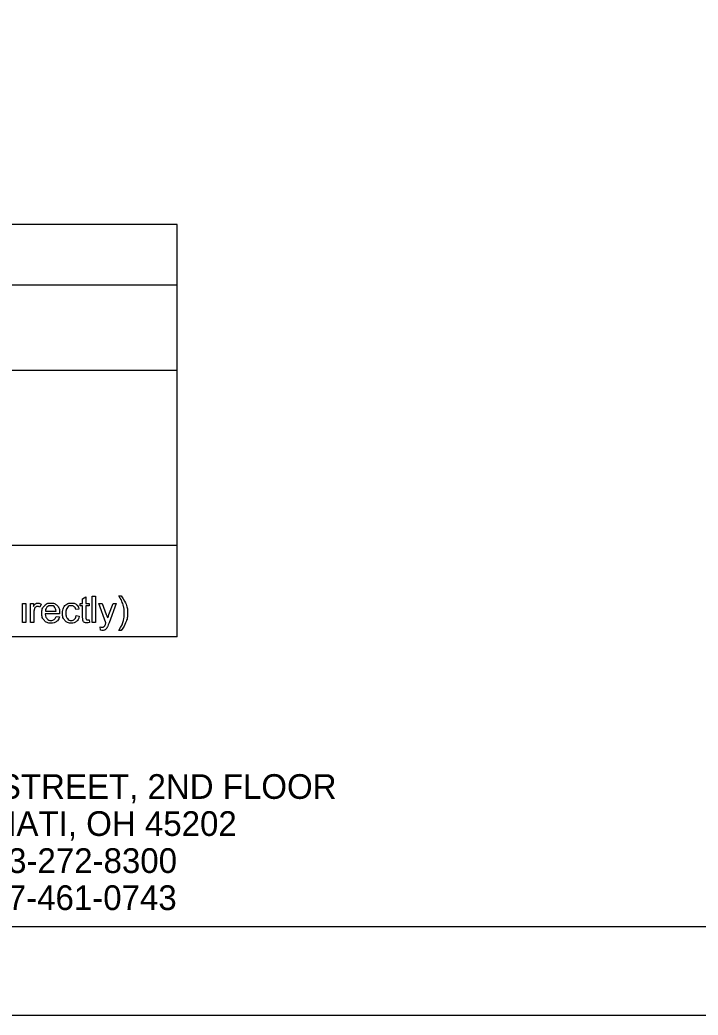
# Model space of a CAD drawing. Extents: x 0 to 34, y 0 to 22.
# Drawn here: x 5.74 to 9.58, y 0 to 5.64 of the extents above; entities that cross this region are included whole.
import ezdxf

# ---------------------------------------------------------------- set-up
doc = ezdxf.new("R2010")
doc.units = 0
for name, color, linetype in [('SH_Border', 7, 'Continuous'), ('SH_Data', 7, 'Continuous'), ('SH_Text', 7, 'Continuous')]:
    doc.layers.add(name, color=color, linetype=linetype)

msp = doc.modelspace()

# ---------------------------------------------------------------- linework, layer by layer
at = {"layer": 'SH_Border'}
msp.add_lwpolyline([(1.5, 21.5), (33.5, 21.5), (33.5, 0.5), (1.5, 0.5)], close=True, dxfattribs=at)
at = {"layer": 'SH_Data'}
for p, q in [((6.6275, 4.4803), (2.3775, 4.4803)), ((6.6275, 2.1428), (6.6275, 4.4803)), ((2.3775, 4.1387), (6.6275, 4.1387)), ((2.3775, 3.6553), (6.6275, 3.6553)), ((6.6275, 2.6607), (2.3775, 2.6607)), ((6.6275, 2.1428), (2.3775, 2.1428))]:
    msp.add_line(p, q, dxfattribs=at)
msp.add_lwpolyline([(0, 0), (34, 0), (34, 22), (0, 22)], close=True, dxfattribs=at)
at = {"layer": 'SH_Text'}
for points in [[(6.092, 2.2558), (6.092, 2.3185), (6.0784, 2.3185), (6.0784, 2.3328), (6.092, 2.3328), (6.092, 2.3597), (6.1105, 2.3708), (6.1105, 2.3328), (6.1289, 2.3328), (6.1289, 2.3185), (6.1105, 2.3185), (6.1105, 2.2547)], [(6.1465, 2.2239), (6.1465, 2.3741), (6.1649, 2.3741), (6.1649, 2.2239), (6.1465, 2.2239)], [(6.2974, 2.3766), (6.3105, 2.3766)], [(5.7509, 2.2239), (5.7509, 2.3328), (5.7693, 2.3328), (5.7693, 2.2239), (5.7509, 2.2239)], [(5.7971, 2.2239), (5.7971, 2.3328), (5.8137, 2.3328), (5.8137, 2.3163)], [(5.8562, 2.3293), (5.8497, 2.3122)], [(6.2243, 2.2238), (6.183, 2.3328), (6.2029, 2.3328), (6.2255, 2.2699)], [(6.241, 2.2693), (6.2643, 2.3328), (6.2827, 2.3328), (6.2414, 2.222)], [(5.8155, 2.2809), (5.8155, 2.2239), (5.7971, 2.2239)], [(5.9611, 2.2736), (5.88, 2.2736)], [(5.881, 2.2887), (5.9418, 2.2887)], [(5.9416, 2.2591), (5.9606, 2.2567)], [(6.0712, 2.3007), (6.0532, 2.298)], [(6.0548, 2.2638), (6.0729, 2.2613)], [(6.1289, 2.2404), (6.1315, 2.2241)], [(6.1928, 2.1821), (6.1907, 2.1995)], [(6.3105, 2.1798), (6.2974, 2.1798)]]:
    msp.add_lwpolyline(points, dxfattribs=at)
for points in [[(6.2974, 2.1798), (6.3279, 2.2289), (6.3279, 2.2782), (6.3279, 2.2974), (6.3235, 2.3164), (6.32, 2.3317), (6.3138, 2.3459), (6.3098, 2.3551), (6.2974, 2.3766)], [(6.3105, 2.3766), (6.3298, 2.3509), (6.339, 2.325), (6.3469, 2.3026), (6.3469, 2.2783), (6.3469, 2.2506), (6.3363, 2.2248), (6.3257, 2.199), (6.3105, 2.1798)], [(5.8137, 2.3163), (5.8201, 2.3278), (5.8254, 2.3315), (5.8308, 2.3352), (5.8372, 2.3352), (5.8466, 2.3352), (5.8562, 2.3293)], [(5.8497, 2.3122), (5.843, 2.3162), (5.8363, 2.3162), (5.8302, 2.3162), (5.8255, 2.3125), (5.8207, 2.3089), (5.8186, 2.3024), (5.8155, 2.2926), (5.8155, 2.2809)], [(5.9606, 2.2567), (5.9561, 2.24), (5.9439, 2.2307), (5.9317, 2.2215), (5.9128, 2.2215), (5.8889, 2.2215), (5.875, 2.2362), (5.861, 2.2509), (5.861, 2.2774), (5.861, 2.3049), (5.8751, 2.32), (5.8892, 2.3352), (5.9118, 2.3352), (5.9336, 2.3352), (5.9474, 2.3203), (5.9612, 2.3055), (5.9612, 2.2785), (5.9612, 2.2769), (5.9611, 2.2736)], [(5.9418, 2.2887), (5.9405, 2.3025), (5.9348, 2.3094), (5.926, 2.3201), (5.912, 2.3201), (5.8993, 2.3201), (5.8906, 2.3115), (5.8819, 2.303), (5.881, 2.2887)], [(6.0729, 2.2613), (6.07, 2.2427), (6.0577, 2.2321), (6.0455, 2.2215), (6.0277, 2.2215), (6.0053, 2.2215), (5.9917, 2.2361), (5.9782, 2.2507), (5.9782, 2.2779), (5.9782, 2.2955), (5.984, 2.3088), (5.9899, 2.322), (6.0018, 2.3286), (6.0137, 2.3352), (6.0278, 2.3352), (6.0455, 2.3352), (6.0568, 2.3262), (6.068, 2.3172), (6.0712, 2.3007)], [(6.0532, 2.298), (6.0507, 2.309), (6.0442, 2.3145), (6.0377, 2.3201), (6.0285, 2.3201), (6.0146, 2.3201), (6.0059, 2.3101), (5.9972, 2.3001), (5.9972, 2.2784), (5.9972, 2.2565), (6.0056, 2.2466), (6.014, 2.2366), (6.0275, 2.2366), (6.0384, 2.2366), (6.0456, 2.2433), (6.0529, 2.2499), (6.0548, 2.2638)], [(5.88, 2.2736), (5.881, 2.2557), (5.8901, 2.2462), (5.8992, 2.2366), (5.9129, 2.2366), (5.923, 2.2366), (5.9302, 2.242), (5.9374, 2.2473), (5.9416, 2.2591)], [(6.2255, 2.2699), (6.2299, 2.258), (6.2334, 2.2448), (6.2366, 2.2572), (6.241, 2.2693)], [(6.1315, 2.2241), (6.1238, 2.2224), (6.1176, 2.2224), (6.1076, 2.2224), (6.1021, 2.2256), (6.0965, 2.2288), (6.0943, 2.234), (6.092, 2.2392), (6.092, 2.2558)], [(6.1105, 2.2547), (6.1105, 2.2468), (6.1114, 2.2445), (6.1124, 2.2423), (6.1146, 2.2409), (6.1168, 2.2396), (6.1209, 2.2396), (6.1239, 2.2396), (6.1289, 2.2404)], [(6.1907, 2.1995), (6.1967, 2.1978), (6.2012, 2.1978), (6.2074, 2.1978), (6.211, 2.1999), (6.2147, 2.2019), (6.2171, 2.2056), (6.2188, 2.2084), (6.2227, 2.2193), (6.2232, 2.2209), (6.2243, 2.2238)], [(6.2414, 2.222), (6.2348, 2.2042), (6.2311, 2.1974), (6.2262, 2.1883), (6.2198, 2.1841), (6.2135, 2.1799), (6.2046, 2.1799), (6.1993, 2.1799), (6.1928, 2.1821)]]:
    msp.add_open_spline(points, degree=3, dxfattribs=at)

# ---------------------------------------------------------------- texts
for s, p in [('1203 WALNUT STREET, 2ND FLOOR', (4.3061, 1.2253)), ('CINCINNATI, OH 45202', (4.9368, 1.0153)), ('T 513-272-8300', (5.2948, 0.8054)), ('F 937-461-0743', (5.2928, 0.5954))]:
    msp.add_text(s, height=0.14, dxfattribs=at).set_placement(p)

doc.saveas('drawing.dxf')
